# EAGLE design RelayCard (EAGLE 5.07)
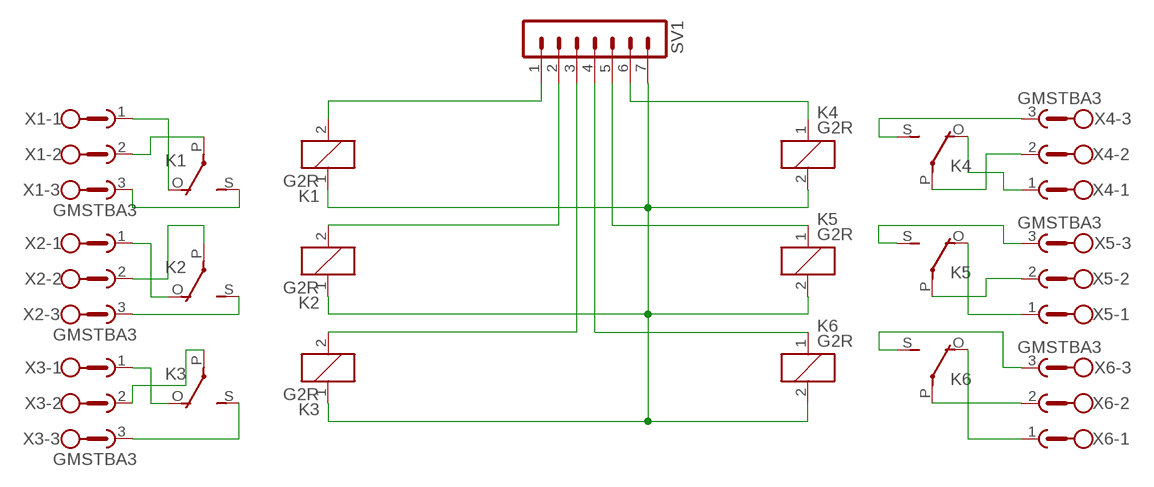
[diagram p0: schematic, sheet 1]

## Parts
K1  G2R  [G2R]
K2  G2R  [G2R]
K3  G2R  [G2R]
K4  G2R  [G2R]
K5  G2R  [G2R]
K6  G2R  [G2R]
SV1  MA07-1  [MA07-1]
X1  GMSTBA3  [GMSTBA3]
X2  GMSTBA3  [GMSTBA3]
X3  GMSTBA3  [GMSTBA3]
X4  GMSTBA3  [GMSTBA3]
X5  GMSTBA3  [GMSTBA3]
X6  GMSTBA3  [GMSTBA3]

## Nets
N$1: K1.S(2:S) X1.3
N$2: K1.O(2:O) X1.1
N$3: K1.P(2:P) X1.2
N$4: K2.O(2:O) X2.1
N$5: K1.2 SV1.1
N$6: K2.2 SV1.2
N$7: K3.2 SV1.3
N$8: K6.1 SV1.4
N$9: K5.1 SV1.5
N$10: K4.1 SV1.6
N$11: K2.S(2:S) X2.3
N$12: K3.O(2:O) X3.1
N$13: K3.S(2:S) X3.3
N$14: K5.O(2:O) X5.1
N$15: K2.P(2:P) X2.2
N$16: K3.P(2:P) X3.2
N$17: K6.O(2:O) X6.1
N$18: K4.P(2:P) X4.2
N$19: K4.S(2:S) X4.3
N$20: K4.O(2:O) X4.1
N$21: K5.P(2:P) X5.2
N$23: K5.S(2:S) X5.3
N$24: K6.P(2:P) X6.2
N$25: K6.S(2:S) X6.3
N$26: K1.1 K2.1 K3.1 K4.2 K5.2 K6.2 SV1.7

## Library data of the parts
K1-K6 = relay:G2R: RELAY 1 x switch, Omron
SV1 = con-lstb:MA07-1: PIN HEADER
X1-X6 = con-phoenix-762:GMSTBA3: PHOENIX

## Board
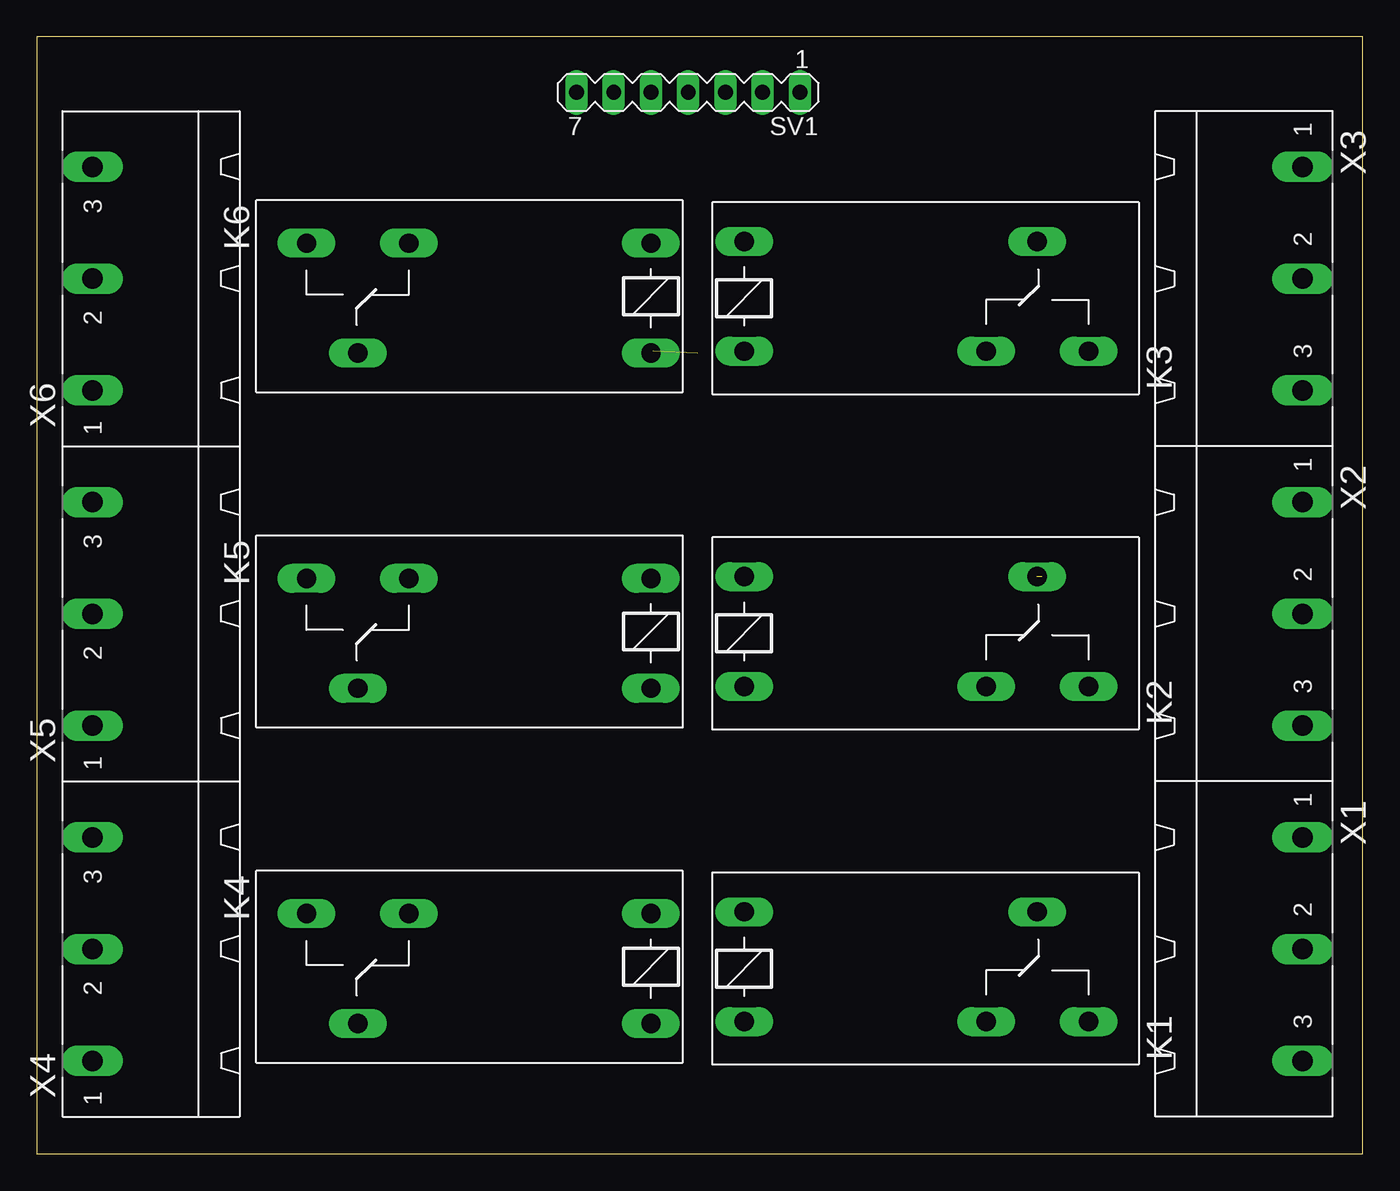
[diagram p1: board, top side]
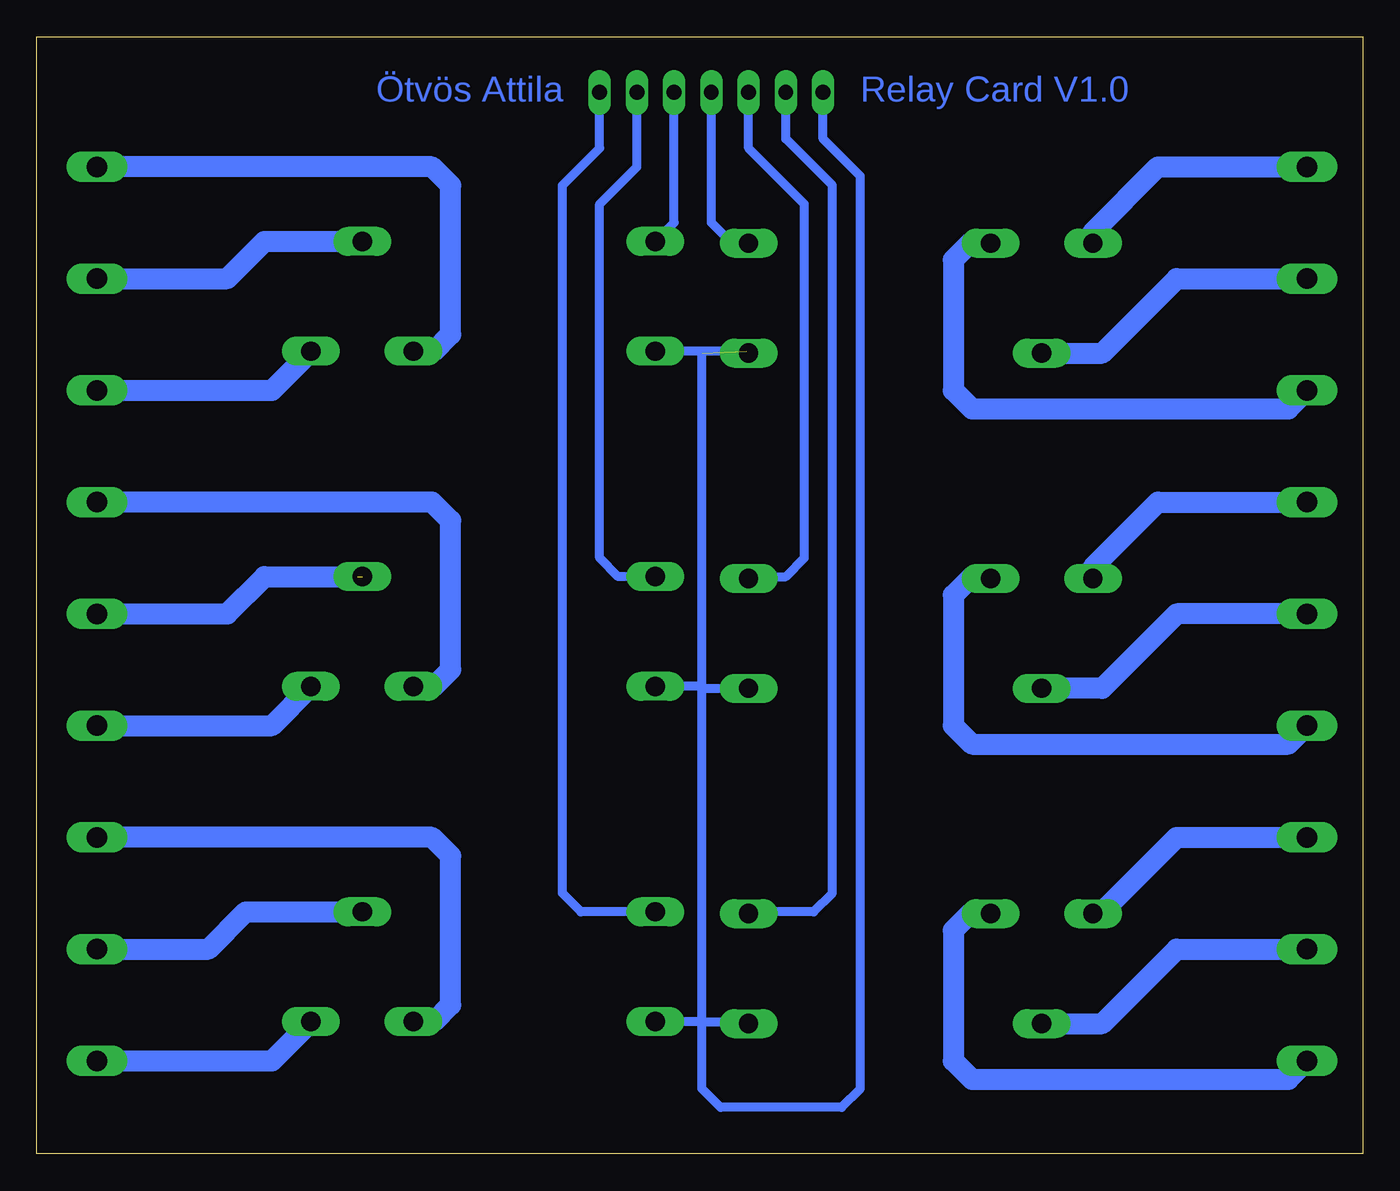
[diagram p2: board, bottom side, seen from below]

Size 90.48 x 76.19 mm. Coordinates in mm from the lower left corner, seen from the top.
Outline: 0,0 90.48,0 90.48,76.19 0,76.19 0,0
Copper layers (1*16): Top 0.035mm / dielectric 1.5mm / Bottom 0.035mm
Design rules "default": minimum track width 10mil, minimum drill 24mil, track to track 8mil, track to pad 8mil, pad to pad 8mil, via to via 8mil, smd to smd 8mil, copper to edge 40mil, drill to drill 8mil, minimum pad ring 10mil, minimum via ring 8mil, stop-mask expansion 4mil, vias tented up to drill 0mil, thermal gap 10mil

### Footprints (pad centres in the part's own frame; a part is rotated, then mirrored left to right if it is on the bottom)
G2R = drill 1.321 long: 1 -2.54,-3.683; 2 -2.54,3.81; O 13.97,-3.683; P 17.45,3.81; S 20.955,-3.683
MA07-1 = drill 1.016 long: 1 -7.62,0; 2 -5.08,0; 3 -2.54,0; 4 0,0; 5 2.54,0; 6 5.08,0; 7 7.62,0
GMSTBA3 = drill 1.397 long: 1 -7.62,5.08; 2 0,5.08; 3 7.62,5.08

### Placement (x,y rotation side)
K1  50.8,12.7 0 top
K2  50.8,35.56 0 top
K3  50.8,58.42 0 top
K4  39.37,12.7 180 top
K5  39.37,35.56 180 top
K6  39.37,58.42 180 top
SV1  44.45,72.39 180 top
X1  81.28,13.97 270 top
X2  81.28,36.83 270 top
X3  81.28,59.69 270 top
X4  8.89,13.97 90 top
X5  8.89,36.83 90 top
X6  8.89,59.69 90 top

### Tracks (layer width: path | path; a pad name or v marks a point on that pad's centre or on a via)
N$1
  Bottom 1.422: X1.3 74.42,6.35 K1.S
N$2
  Bottom 1.422: K1.O 63.37,9.02 62.23,10.16 62.23,20.32 63.5,21.59 X1.1
N$3
  Bottom 1.422: X1.2 78.74,13.97 76.2,16.51 K1.P
N$4
  Bottom 1.422: K2.O 63.37,31.88 62.23,33.02 62.23,43.18 63.5,44.45 X2.1
N$5
  Bottom 0.61: K1.2 53.34,16.51 54.61,17.78 54.61,66.04 52.07,68.58 SV1.1
N$6
  Bottom 0.61: K2.2 50.8,39.37 52.07,40.64 52.07,64.77 49.53,67.31 SV1.2
N$7
  Bottom 0.61: K3.2 46.99,63.5 SV1.3
N$8
  Bottom 0.61: K6.1 42.04,62.23 43.18,62.23 44.45,63.5 SV1.4
N$9
  Bottom 0.61: K5.1 41.78,39.37 39.37,39.37 38.1,40.64 38.1,64.77 41.91,68.58 SV1.5
N$10
  Bottom 0.61: K4.1 41.78,16.51 37.46,16.51 36.2,17.78 36.2,66.04 39.37,69.22 SV1.6
N$11
  Bottom 1.422: X2.3 74.42,29.21 K2.S
N$12
  Bottom 1.422: K3.O 63.37,54.74 62.23,55.88 62.23,66.04 63.5,67.31 X3.1
N$13
  Bottom 1.422: X3.3 74.42,52.07 K3.S
N$14
  Bottom 1.422: K5.O 26.54,39.24 26.67,39.37 27.94,38.1 27.94,29.21 26.67,27.94 5.08,27.94 X5.1
N$15  (1 unrouted)
  Bottom 1.422: X2.2 77.47,36.83 74.93,39.37 68.58,39.37
N$16
  Bottom 1.422: X3.2 77.47,59.69 74.93,62.23 K3.P
N$17
  Bottom 1.422: K6.O 26.8,62.1 27.94,60.96 27.94,52.07 26.67,50.8 5.08,50.8 X6.1
N$18
  Bottom 1.422: K4.P 17.78,8.89 12.7,13.97 X4.2
N$19
  Bottom 1.422: K4.S 17.91,16.38 12.7,21.59 X4.3
N$20
  Bottom 1.422: K4.O 26.8,16.38 27.94,15.24 27.94,6.35 26.67,5.08 5.08,5.08 X4.1
N$21
  Bottom 1.422: X5.2 12.7,36.83 17.78,31.75 K5.P
N$23
  Bottom 1.422: K5.S 18.41,40 13.97,44.45 X5.3
N$24
  Bottom 1.422: K6.P 17.78,54.61 12.7,59.69 X6.2
N$25
  Bottom 1.422: K6.S 18.41,62.86 13.97,67.31 X6.3
N$26  (1 unrouted)
  Bottom 0.61: K3.1 42.04,54.74 K6.2 | 45.09,9.02 42.04,9.02 K4.2 | 45.09,9.02 K1.1 | SV1.7 36.83,69.22 34.29,66.67 34.29,4.45 35.56,3.18 43.81,3.18 45.09,4.45 45.09,9.02 | 45.09,9.02 45.09,31.75 | 45.09,31.75 45.09,54.61 | K2.1 45.21,31.88 45.09,31.75 | 45.09,31.75 K5.2

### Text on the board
Bottom: Relay Card V1.0 | Ötvös Attila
